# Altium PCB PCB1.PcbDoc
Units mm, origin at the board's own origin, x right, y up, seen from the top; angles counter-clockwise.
Board outline 152.4 x 101.6 mm, 2 copper layers (Top Layer, Bottom Layer); 12 components, 0 nets, 103 pads, 0 vias.
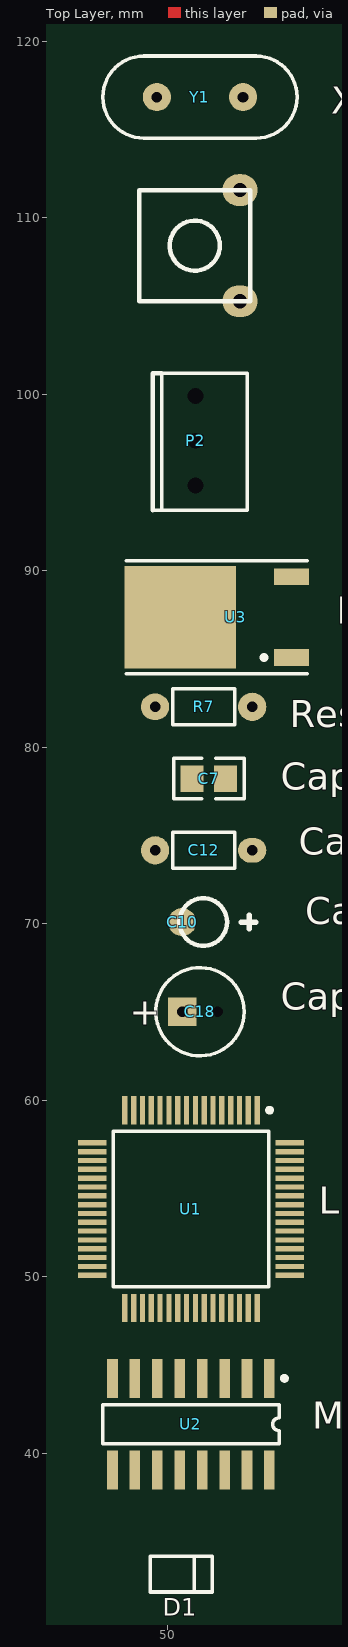
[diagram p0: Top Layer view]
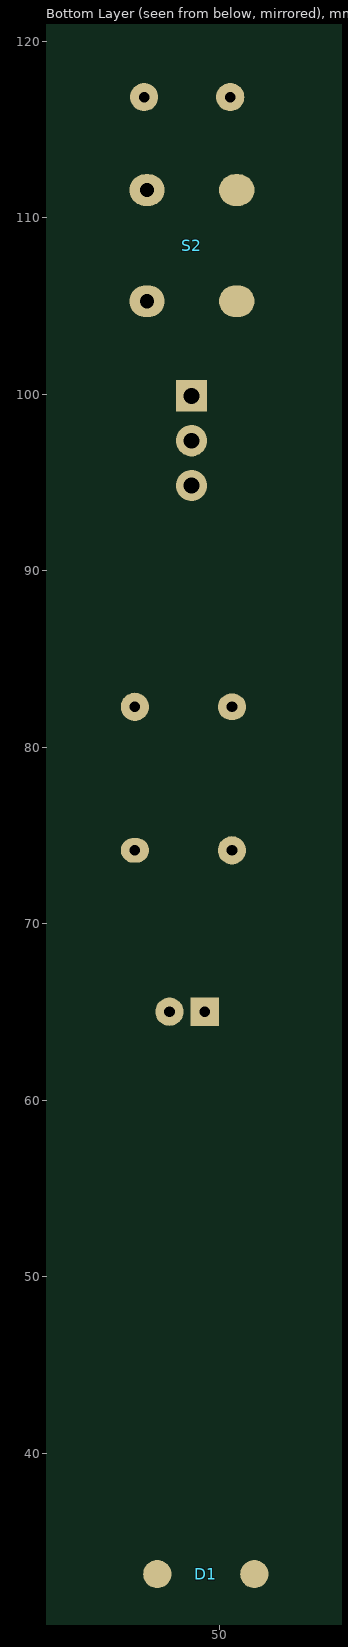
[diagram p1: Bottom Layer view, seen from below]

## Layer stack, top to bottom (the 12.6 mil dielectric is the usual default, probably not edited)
Top Layer: signal copper 0.0356
Dielectric: dielectric 0.32, FR-4, Dk 4.8
Bottom Layer: signal copper 0.0356

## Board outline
25.4,25.4 177.8,25.4 177.8,127 25.4,127

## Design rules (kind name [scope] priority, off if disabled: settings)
Clearance [All] p1: gap=0.254
ComponentClearance [All] p1: gap=0.254 collisioncheckmode=3 verticalgap=0.254
PolygonConnect [All] p1: connectstyle=Relief reliefconductorwidth=0.254 reliefentries=4 polygonreliefangle="90 Angle"
RoutingVias [All] p1: holewidth=0.711 width=1.27 viastyle="Through Hole" minholewidth=0.711 minwidth=1.27 maxholewidth=0.711 maxwidth=1.27
SolderMaskExpansion [All] p1: expansion=0.102
TestPointUsage [All] p1: valid=0 allowmultiple=FALSE
Testpoint [All] p1: side=15 testpointundercomponent=TRUE minsize=1.016 maxsize=2.54 preferedsize=1.524 minholesize=0 maxholesize=1.016 preferedholesize=0.813 testpointgrid=0.025 style=1023 order=0-112345678
Width [All] p1: maxlimit=0.254 minlimit=0.254 preferedwidth=0.254
18 further rules are at their usual default settings.

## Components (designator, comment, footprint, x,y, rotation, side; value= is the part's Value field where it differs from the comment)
C7 "Cap SMD" R2012-0805 52.324,78.232 r0 top
C10 "Cap Pol tantalio" CAP_ELECT1 53.34,70.104 r180 top
C12 "Cap ceramico" "Res 5mm"#1 49.276,74.168 r0 top
C18 "Cap Pol electrolitico" CAPPR2-5x6.8 51.816,65.024 r0 top
D1 "Diode" "Diode 5mm" 48.008,33.17 r0 top
P2 "WF3S" WF3S 50.932,98.896 r270 top
R7 "Res 5mm" "Res 5mm"#2 49.276,82.296 r0 top
S2 "SW-PB" SW1 48.371,105.272 r0 top
U1 "LPC2114/LPC2124" F-QFP10X10-G64/P.5N 51.308,53.848 r270 top
U2 "MAX232EWE" SO-G16 51.308,41.656 r180 top
U3 "LD1117S18" KTP02 53.848,87.376 r90 top
Y1 "XTAL 12Mhz" Cristal_Low_Profile 51.816,116.84 r180 top

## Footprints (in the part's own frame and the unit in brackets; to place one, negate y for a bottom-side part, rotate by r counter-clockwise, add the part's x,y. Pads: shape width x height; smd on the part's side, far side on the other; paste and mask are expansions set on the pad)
CAP_ELECT1 [mm] "Capacitor, Radial, Tantalum; Body 2.54 x 5.72 mm (Dia.xH max); Pin Spacing 1.78 mm (typ)"
  round 1.6 smd: 2(2.54,0)
  silkscreen extent -1.65,-1.34 2.68,1.34
CAPPR2-5x6.8 [mm] "Capacitor, Electrolytic, Radial; Body 5 x 6.8 mm (Dia.xH typ); Pin Spacing 2 mm (typ)"
  rect 1.6x1.6 hole 0.6: 1(-1,0)
  round 0 / inner round 0 / far side round 1.6 hole 0.6: 2(1,0)
  silkscreen extent -2.5,-2.5 2.5,2.5
Cristal_Low_Profile [mm]
  round 1.6 hole 0.6: 1(-2.44,0) 2(2.44,0)
  silkscreen extent -5.5,-2.32 5.5,2.32
"Diode 5mm" [mm]
  round 1.6 smd far side: 1(0,0) 2(5.5,0)
  silkscreen extent 1,-1.02 4.5,1.02
F-QFP10X10-G64/P.5N [mm]
  rect 1.6x0.3 smd: 1(-5.6,3.75) 2(-5.6,3.25) 3(-5.6,2.75) 4(-5.6,2.25) 5(-5.6,1.75) 6(-5.6,1.25) 7(-5.6,0.75) 8(-5.6,0.25) 9(-5.6,-0.25) 10(-5.6,-0.75) 11(-5.6,-1.25) 12(-5.6,-1.75) 13(-5.6,-2.25) 14(-5.6,-2.75) 15(-5.6,-3.25) 16(-5.6,-3.75) 33(5.6,-3.75) 34(5.6,-3.25) 35(5.6,-2.75) 36(5.6,-2.25) 37(5.6,-1.75) 38(5.6,-1.25) 39(5.6,-0.75) 40(5.6,-0.25) 41(5.6,0.25) 42(5.6,0.75) 43(5.6,1.25) 44(5.6,1.75) 45(5.6,2.25) 46(5.6,2.75) 47(5.6,3.25) 48(5.6,3.75)
  rect 0.3x1.6 smd: 17(-3.75,-5.6) 18(-3.25,-5.6) 19(-2.75,-5.6) 20(-2.25,-5.6) 21(-1.75,-5.6) 22(-1.25,-5.6) 23(-0.75,-5.6) 24(-0.25,-5.6) 25(0.25,-5.6) 26(0.75,-5.6) 27(1.25,-5.6) 28(1.75,-5.6) 29(2.25,-5.6) 30(2.75,-5.6) 31(3.25,-5.6) 32(3.75,-5.6) 49(3.75,5.6) 50(3.25,5.6) 51(2.75,5.6) 52(2.25,5.6) 53(1.75,5.6) 54(1.25,5.6) 55(0.75,5.6) 56(0.25,5.6) 57(-0.25,5.6) 58(-0.75,5.6) 59(-1.25,5.6) 60(-1.75,5.6) 61(-2.25,5.6) 62(-2.75,5.6) 63(-3.25,5.6) 64(-3.75,5.6)
  silkscreen extent -5.72,-4.4 4.4,4.58
KTP02 [mm] "PowerFLEX (D-PAK/TO-252-AA); 3 Leads (1 Cropped); Body 9.7 (inc. leads) x 6.2 mm (LxW max)"
  rect 0.95x2 smd: 1(-2.285,-3.15) 3(2.285,-3.15)
  rect 5.8x6.3 smd: 4(0,3.15)
  silkscreen extent -3.2,-4.05 3.2,6.2
R2012-0805 [mm]
  rect 1.3x1.5 smd: 1(-0.95,0) 2(0.95,0)
  silkscreen extent -2,-1.15 2,1.15
"Res 5mm"#1 [mm]
  round 1.6 hole 0.6: 1(0,0)
  oval 1.6x1.4 hole 0.6: 2(5.5,0)
  silkscreen extent 1,-1.02 4.5,1.02
"Res 5mm"#2 [mm]
  oval 1.6x1.5 hole 0.6: 1(0,0)
  round 1.6 hole 0.6: 2(5.5,0)
  silkscreen extent 1,-1.02 4.5,1.02
SO-G16 [mm]
  rect 0.6x2.2 smd: 1(-4.445,-2.6) 2(-3.175,-2.6) 3(-1.905,-2.6) 4(-0.635,-2.6) 5(0.635,-2.6) 6(1.905,-2.6) 7(3.175,-2.6) 8(4.445,-2.6) 9(4.445,2.6) 10(3.175,2.6) 11(1.905,2.6) 12(0.635,2.6) 13(-0.635,2.6) 14(-1.905,2.6) 15(-3.175,2.6) 16(-4.445,2.6)
  silkscreen extent -5.42,-2.72 5,1.1
SW1 [mm]
  oval 2x1.8 smd far side: 1(0.635,0) 1(0.635,6.3)
  oval 2x1.8 hole 0.8: 2(5.715,0) 2(5.715,6.3)
  silkscreen extent 0,0 6.3,6.3
WF3S [mm]
  round 0 / inner round 0 / far side rect 1.778x1.778 hole 0.9: 1(-1.016,0.635)
  round 0 / inner round 0 / far side round 1.778 hole 0.9: 2(1.524,0.635) 3(4.064,0.635)
  silkscreen extent -2.29,-1.78 5.46,3.56

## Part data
C7 C12: library part Cap, "Capacitor"
C10: library part "Cap Pol3", "Polarized Capacitor (Surface Mount)"
C18: library part "Cap Pol1", "Polarized Capacitor (Radial)"
D1: "Default Diode"
P2: library part "Header 3", "Header, 3-Pin"
R7: library part Res1, "Resistor"
S2: "Switch"
U2: "+5V Powered RS-232 Driver/Receiver"
U3: library part LF27ACDT, "Very Low Drop Voltage Regulator with Inhibit"
Y1: library part XTAL, "Crystal Oscillator"

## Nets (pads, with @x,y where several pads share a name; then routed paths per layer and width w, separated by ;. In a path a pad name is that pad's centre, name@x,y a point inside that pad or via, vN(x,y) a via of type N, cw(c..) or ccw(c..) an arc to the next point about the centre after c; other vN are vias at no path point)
pads on no net: C7.1 C7.2 C10.2 C12.1 C12.2 C18.1 C18.2 D1.1 D1.2 P2.1 P2.2 P2.3 R7.1 R7.2 S2.1 S2.2 U1.1 U1.2 U1.3 U1.4 U1.5 U1.6 U1.7 U1.8 U1.9 U1.10 U1.11 U1.12 U1.13 U1.14 U1.15 U1.16 U1.17 U1.18 U1.19 U1.20 U1.21 U1.22 U1.23 U1.24 U1.25 U1.26 U1.27 U1.28 U1.29 U1.30 U1.31 U1.32 U1.33 U1.34 U1.35 U1.36 U1.37 U1.38 U1.39 U1.40 U1.41 U1.42 U1.43 U1.44 U1.45 U1.46 U1.47 U1.48 U1.49 U1.50 U1.51 U1.52 U1.53 U1.54 U1.55 U1.56 U1.57 U1.58 U1.59 U1.60 U1.61 U1.62 U1.63 U1.64 U2.1 U2.2 U2.3 U2.4 U2.5 U2.6 U2.7 U2.8 U2.9 U2.10 U2.11 U2.12 U2.13 U2.14 U2.15 U2.16 U3.1 U3.3 U3.4 Y1.1 Y1.2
